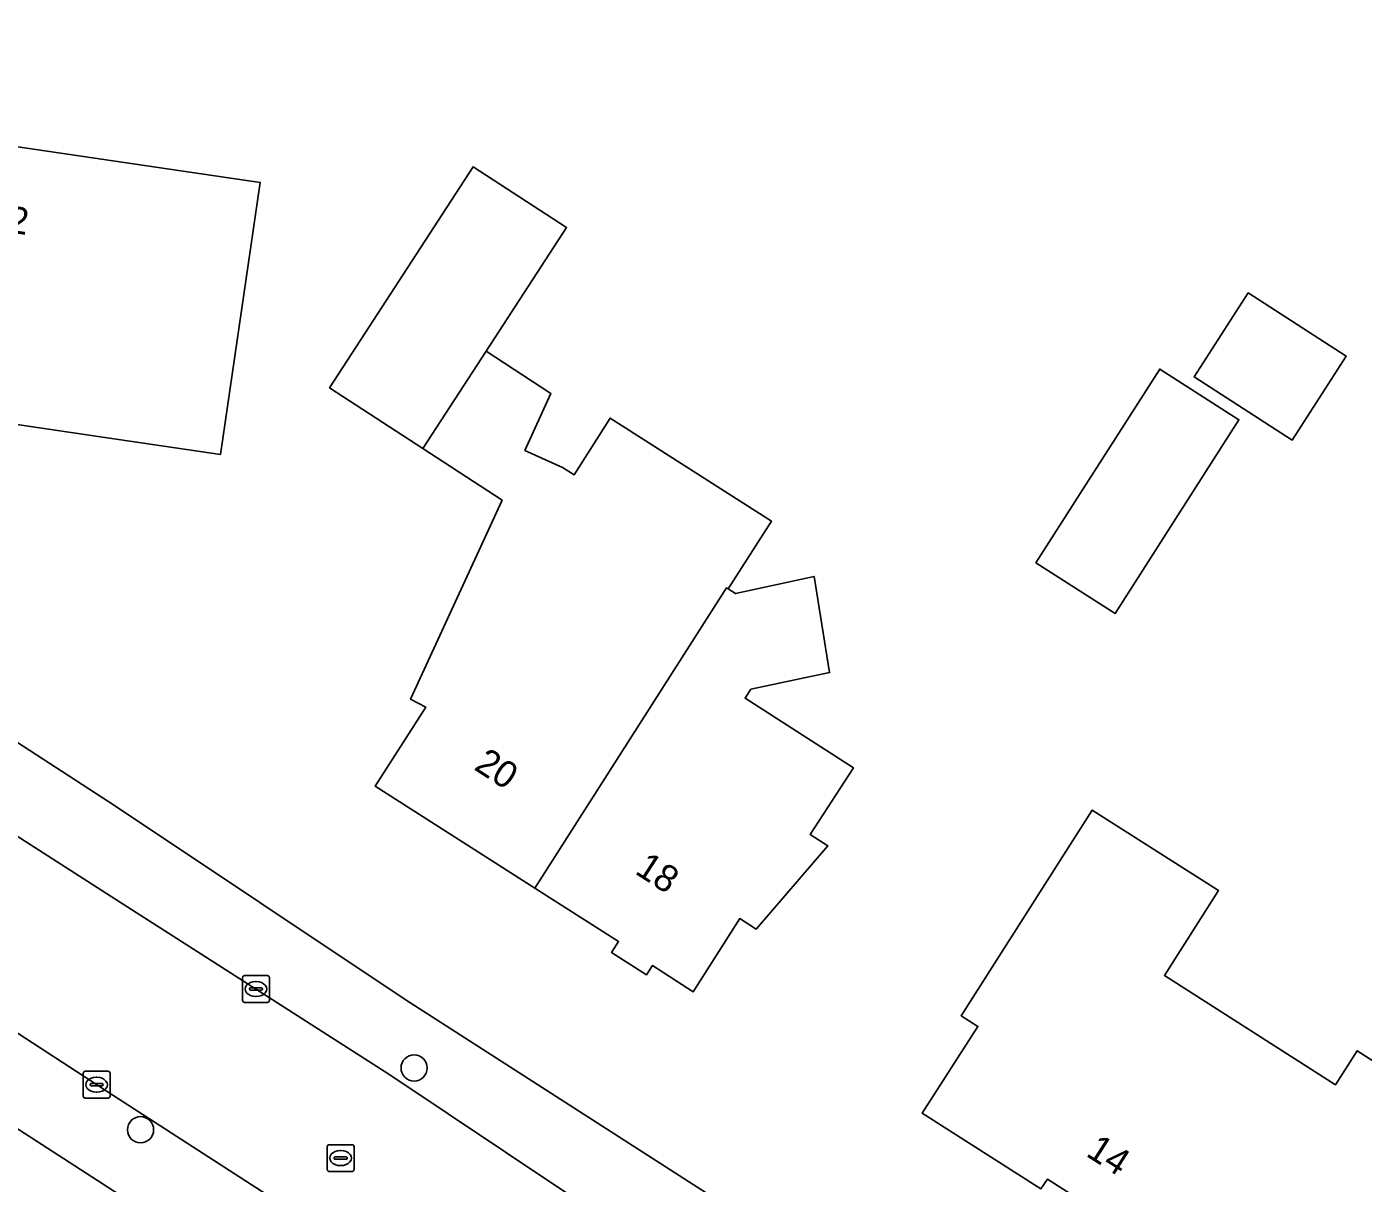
# Model space of a CAD drawing. Extents: x 161139 to 161601, y 381708 to 382245.
# Drawn here: x 161296.54 to 161346.45, y 381974.24 to 382017.42 of the extents above; entities that cross this region are included whole.
import ezdxf

# ---------------------------------------------------------------- set-up
doc = ezdxf.new("R2010")
doc.units = 0
for name, color, linetype in [('IMGEO_Boom', 7, 'Continuous'), ('IMGEO_Erf', 7, 'Continuous'), ('IMGEO_Kolk', 7, 'Continuous'), ('IMGEO_Pand', 7, 'Continuous'), ('IMGEO_Pand_nummerreeks', 7, 'Continuous'), ('IMGEO_Rijbaan_lokaal_open', 7, 'Continuous'), ('IMGEO_Rioolput', 7, 'Continuous'), ('IMGEO_Voetpad_open', 7, 'Continuous')]:
    doc.layers.add(name, color=color, linetype=linetype)

msp = doc.modelspace()

# ---------------------------------------------------------------- linework, layer by layer
at = {"layer": 'IMGEO_Boom'}
for centre in [(161311.007, 381978.547), (161300.792, 381976.24)]:
    msp.add_circle(centre, 0.489, dxfattribs=at)
at = {"layer": 'IMGEO_Erf'}
for points in [[(161301.893, 382073.339), (161290.838, 382055.877), (161287.538, 382048.363), (161285.187, 382041.077), (161283.628, 382034.817), (161278.294, 382002.287), (161281.877, 382000), (161299.823, 381988.353), (161310.674, 381981.109), (161322.611, 381973.432), (161322.712, 381973.551), (161378.924, 381936.994), (161385.641, 381932.206), (161392.817, 381926.552), (161429.313, 381896.994)], [(161370.462, 381928.258), (161276.309, 381989.126), (161276.14, 381989.025), (161267.873, 381937.797), (161267.435, 381933.784), (161267.467, 381929.855), (161267.871, 381925.589), (161268.634, 381921.624), (161269.796, 381917.444), (161271.533, 381912.948), (161272.783, 381910.378), (161277.045, 381903.774)]]:
    msp.add_lwpolyline(points, dxfattribs=at)
for points in [[(161303.775, 382001.453), (161299.54, 382002.074), (161295.582, 382002.654), (161295.956, 382005.206), (161293.903, 382005.507), (161294.186, 382007.443), (161286.609, 382008.553), (161287.441, 382014.225), (161292.389, 382013.5), (161301.029, 382012.233), (161305.264, 382011.612)], [(161322.733, 381996.437), (161323.014, 381996.257), (161325.944, 381996.899), (161326.519, 381993.307), (161323.584, 381992.685), (161323.366, 381992.35), (161327.411, 381989.759), (161325.791, 381987.268), (161326.455, 381986.845), (161323.779, 381983.735), (161323.17, 381984.124), (161321.429, 381981.396), (161319.905, 381982.369), (161319.684, 381982.022), (161318.379, 381982.855), (161318.642, 381983.266), (161315.516, 381985.262), (161309.559, 381989.066), (161311.443, 381992.018), (161310.875, 381992.313), (161314.292, 381999.751), (161311.336, 382001.672), (161307.849, 382003.938), (161313.212, 382012.191), (161316.699, 382009.925), (161313.698, 382005.307), (161316.118, 382003.727), (161315.145, 382001.608), (161316.552, 382000.963), (161316.978, 382000.69), (161318.331, 382002.81), (161324.352, 381998.967)], [(161343.792, 382001.991), (161340.135, 382004.348), (161342.156, 382007.484), (161345.814, 382005.126)], [(161337.186, 381995.52), (161334.228, 381997.409), (161335.883, 382000), (161338.848, 382004.642), (161341.806, 382002.753)], [(161345.229, 381971.099), (161345.094, 381971.185), (161344.863, 381970.822), (161342.904, 381972.07), (161342.662, 381971.691), (161342.021, 381972.099), (161340.338, 381969.467), (161336.1, 381972.176), (161336.689, 381973.098), (161334.659, 381974.396), (161334.413, 381974.038), (161329.982, 381976.855), (161332.06, 381980.096), (161331.431, 381980.495), (161336.33, 381988.176), (161341.044, 381985.169), (161339.024, 381982.002), (161345.419, 381977.923), (161346.226, 381979.188), (161349.184, 381977.301)]]:
    msp.add_lwpolyline(points, close=True, dxfattribs=at)
at = {"layer": 'IMGEO_Kolk'}
for p, q in [((161304.601, 381981.069), (161304.601, 381981.921)), ((161304.676, 381981.995), (161305.528, 381981.995)), ((161305.602, 381981.921), (161305.602, 381981.069)), ((161304.86, 381981.489), (161304.86, 381981.501)), ((161305.298, 381981.452), (161304.9, 381981.452)), ((161304.903, 381981.538), (161305.301, 381981.538)), ((161305.089, 381981.775), (161305.114, 381981.775)), ((161305.344, 381981.501), (161305.344, 381981.489)), ((161305.528, 381980.995), (161304.676, 381980.995)), ((161305.112, 381981.215), (161305.087, 381981.215)), ((161298.726, 381978.422), (161299.578, 381978.422)), ((161298.651, 381977.496), (161298.651, 381978.348)), ((161298.91, 381977.916), (161298.91, 381977.928)), ((161299.348, 381977.879), (161298.95, 381977.879)), ((161298.953, 381977.965), (161299.351, 381977.965)), ((161299.139, 381978.202), (161299.164, 381978.202)), ((161299.394, 381977.928), (161299.394, 381977.916)), ((161299.652, 381978.348), (161299.652, 381977.496)), ((161299.578, 381977.422), (161298.726, 381977.422)), ((161299.162, 381977.642), (161299.137, 381977.642))]:
    msp.add_line(p, q, dxfattribs=at)
for points in [[(161304.601, 381981.069), (161304.601, 381981.921)], [(161304.676, 381981.995), (161305.528, 381981.995)], [(161305.602, 381981.921), (161305.602, 381981.069)], [(161305.528, 381980.995), (161304.676, 381980.995)], [(161298.726, 381978.422), (161299.578, 381978.422)], [(161298.651, 381977.496), (161298.651, 381978.348)], [(161299.652, 381978.348), (161299.652, 381977.496)], [(161299.578, 381977.422), (161298.726, 381977.422)]]:
    msp.add_lwpolyline(points, dxfattribs=at)
for centre, radius, start, end in [((161304.678, 381981.919), 0.0765, 91.552, 178.448), ((161304.678, 381981.919), 0.0765, 91.552, 178.448), ((161305.526, 381981.919), 0.0765, 1.552, 88.448), ((161305.526, 381981.919), 0.0765, 1.552, 88.448), ((161304.9, 381981.498), 0.0403, 85.8775, 175.7526), ((161304.897, 381981.488), 0.0366, 178.938, 274.7102), ((161305.301, 381981.495), 0.043, 264.8664, 352.4533), ((161305.305, 381981.5), 0.0386, 1.7309, 96.639), ((161304.678, 381981.071), 0.0765, 181.552, 268.448), ((161304.678, 381981.071), 0.0765, 181.552, 268.448), ((161305.526, 381981.071), 0.0765, 271.552, 358.448), ((161305.526, 381981.071), 0.0765, 271.552, 358.448), ((161298.728, 381978.346), 0.0765, 91.552, 178.448), ((161298.728, 381978.346), 0.0765, 91.552, 178.448), ((161299.576, 381978.346), 0.0765, 1.552, 88.448), ((161299.576, 381978.346), 0.0765, 1.552, 88.448), ((161298.95, 381977.925), 0.0403, 85.8775, 175.7526), ((161298.947, 381977.915), 0.0366, 178.938, 274.7102), ((161299.351, 381977.922), 0.043, 264.8664, 352.4533), ((161299.355, 381977.927), 0.0386, 1.7309, 96.639), ((161298.728, 381977.498), 0.0765, 181.552, 268.448), ((161298.728, 381977.498), 0.0765, 181.552, 268.448), ((161299.576, 381977.498), 0.0765, 271.552, 358.448), ((161299.576, 381977.498), 0.0765, 271.552, 358.448)]:
    msp.add_arc(centre, radius, start, end, dxfattribs=at)
for centre, major_axis, ratio, start_param, end_param in [((161305.088, 381981.495), (-0.387, 0.002), 0.722429, 4.712389, 7.853982), ((161305.113, 381981.495), (-0.39, 0.002), 0.717154, 1.570796, 4.712389), ((161299.138, 381977.922), (-0.387, 0.002), 0.722429, 4.712389, 7.853982), ((161299.163, 381977.922), (-0.39, 0.002), 0.717154, 1.570796, 4.712389)]:
    msp.add_ellipse(centre, major_axis=major_axis, ratio=ratio, start_param=start_param, end_param=end_param, dxfattribs=at)
at = {"layer": 'IMGEO_Pand'}
for points in [[(161292.389, 382013.5), (161287.441, 382014.225), (161286.609, 382008.553), (161294.186, 382007.443), (161293.903, 382005.507), (161295.956, 382005.206), (161295.582, 382002.654), (161299.54, 382002.074), (161303.775, 382001.453), (161305.264, 382011.612), (161301.029, 382012.233)], [(161316.699, 382009.925), (161313.212, 382012.191), (161307.849, 382003.938), (161311.336, 382001.672), (161313.698, 382005.307)], [(161342.156, 382007.484), (161340.135, 382004.348), (161343.792, 382001.991), (161345.814, 382005.126)], [(161322.589, 381996.335), (161322.677, 381996.473), (161322.733, 381996.437), (161324.352, 381998.967), (161318.331, 382002.81), (161316.978, 382000.69), (161316.552, 382000.963), (161315.145, 382001.608), (161316.118, 382003.727), (161313.698, 382005.307), (161311.336, 382001.672), (161314.292, 381999.751), (161310.875, 381992.313), (161311.443, 381992.018), (161309.559, 381989.066), (161315.516, 381985.262)], [(161341.806, 382002.753), (161338.848, 382004.642), (161335.883, 382000), (161334.228, 381997.409), (161337.186, 381995.52)], [(161327.411, 381989.759), (161323.366, 381992.35), (161323.584, 381992.685), (161326.519, 381993.307), (161325.944, 381996.899), (161323.014, 381996.257), (161322.733, 381996.437), (161322.677, 381996.473), (161322.589, 381996.335), (161315.516, 381985.262), (161318.642, 381983.266), (161318.379, 381982.855), (161319.684, 381982.022), (161319.905, 381982.369), (161321.429, 381981.396), (161323.17, 381984.124), (161323.779, 381983.735), (161326.455, 381986.845), (161325.791, 381987.268)], [(161349.184, 381977.301), (161346.226, 381979.188), (161345.419, 381977.923), (161339.024, 381982.002), (161341.044, 381985.169), (161336.33, 381988.176), (161331.431, 381980.495), (161332.06, 381980.096), (161329.982, 381976.855), (161334.413, 381974.038), (161334.659, 381974.396), (161336.689, 381973.098), (161336.1, 381972.176), (161340.338, 381969.467), (161342.021, 381972.099), (161342.662, 381971.691), (161342.904, 381972.07), (161344.863, 381970.822), (161345.094, 381971.185), (161345.229, 381971.099)]]:
    msp.add_lwpolyline(points, close=True, dxfattribs=at)
at = {"layer": 'IMGEO_Rijbaan_lokaal_open'}
for points in [[(161354.44, 381949.434), (161345.5, 381955.194), (161345.132, 381955.433), (161341.968, 381957.49), (161334.965, 381962.043), (161325.373, 381968.263), (161318.237, 381972.89), (161316.637, 381973.927), (161310.106, 381978.294), (161303.837, 381982.304), (161300.012, 381984.75), (161296.327, 381987.12), (161278.737, 381998.431)], [(161278.323, 381991.478), (161299.753, 381977.533), (161307.482, 381972.536), (161311.114, 381970.18), (161315.062, 381967.62), (161315.173, 381967.548), (161318.89, 381965.138), (161327.462, 381959.489), (161330.866, 381957.332), (161337.714, 381952.958), (161346.638, 381947.161), (161350.625, 381944.584), (161357.825, 381939.931), (161366.222, 381934.52), (161372.037, 381930.857), (161375.083, 381928.811)]]:
    msp.add_lwpolyline(points, dxfattribs=at)
at = {"layer": 'IMGEO_Rioolput'}
for p, q in [((161307.763, 381974.755), (161307.763, 381975.607)), ((161307.838, 381975.681), (161308.69, 381975.681)), ((161308.251, 381975.461), (161308.276, 381975.461)), ((161308.764, 381975.607), (161308.764, 381974.755)), ((161308.022, 381975.175), (161308.022, 381975.187)), ((161308.46, 381975.138), (161308.062, 381975.138)), ((161308.065, 381975.224), (161308.463, 381975.224)), ((161308.274, 381974.901), (161308.249, 381974.901)), ((161308.506, 381975.187), (161308.506, 381975.175)), ((161308.69, 381974.681), (161307.838, 381974.681))]:
    msp.add_line(p, q, dxfattribs=at)
for points in [[(161307.763, 381974.755), (161307.763, 381975.607)], [(161307.838, 381975.681), (161308.69, 381975.681)], [(161308.764, 381975.607), (161308.764, 381974.755)], [(161308.69, 381974.681), (161307.838, 381974.681)]]:
    msp.add_lwpolyline(points, dxfattribs=at)
for centre, radius, start, end in [((161307.84, 381975.605), 0.0765, 91.552, 178.448), ((161307.84, 381975.605), 0.0765, 91.552, 178.448), ((161308.688, 381975.605), 0.0765, 1.552, 88.448), ((161308.688, 381975.605), 0.0765, 1.552, 88.448), ((161308.062, 381975.184), 0.0403, 85.8775, 175.7526), ((161308.059, 381975.174), 0.0366, 178.938, 274.7102), ((161308.463, 381975.181), 0.043, 264.8664, 352.4533), ((161308.467, 381975.186), 0.0386, 1.7309, 96.639), ((161307.84, 381974.757), 0.0765, 181.552, 268.448), ((161307.84, 381974.757), 0.0765, 181.552, 268.448), ((161308.688, 381974.757), 0.0765, 271.552, 358.448), ((161308.688, 381974.757), 0.0765, 271.552, 358.448)]:
    msp.add_arc(centre, radius, start, end, dxfattribs=at)
for centre, major_axis, ratio, start_param, end_param in [((161308.25, 381975.181), (-0.387, 0.002), 0.722429, 4.712389, 7.853982), ((161308.275, 381975.181), (-0.39, 0.002), 0.717154, 1.570796, 4.712389)]:
    msp.add_ellipse(centre, major_axis=major_axis, ratio=ratio, start_param=start_param, end_param=end_param, dxfattribs=at)
at = {"layer": 'IMGEO_Voetpad_open'}
for points in [[(161392.817, 381926.552), (161385.641, 381932.206), (161378.924, 381936.994), (161322.712, 381973.551), (161322.611, 381973.432), (161310.674, 381981.109), (161299.823, 381988.353), (161281.877, 382000)], [(161327.462, 381959.489), (161318.89, 381965.138), (161315.173, 381967.548), (161315.062, 381967.62), (161311.114, 381970.18), (161307.482, 381972.536), (161299.753, 381977.533), (161278.323, 381991.478), (161276.309, 381989.126), (161370.462, 381928.258), (161376.195, 381924.445)], [(161296.327, 381987.12), (161300.012, 381984.75), (161303.837, 381982.304), (161310.106, 381978.294), (161316.637, 381973.927), (161318.237, 381972.89), (161325.373, 381968.263), (161334.965, 381962.043), (161341.968, 381957.49), (161345.132, 381955.433), (161345.5, 381955.194), (161354.44, 381949.434), (161361.946, 381944.451), (161364.318, 381942.933), (161367.432, 381940.939), (161370.251, 381939.135), (161376.383, 381935.18), (161381.315, 381931.756), (161381.728, 381931.469), (161384.971, 381929.006)]]:
    msp.add_lwpolyline(points, dxfattribs=at)

# ---------------------------------------------------------------- texts
at = {"layer": 'IMGEO_Pand_nummerreeks'}
for s, rotation, p in [('22', 351.6657, (161295.065, 382009.861)), ('20', 327.1294, (161313.203, 381989.712)), ('18', 327.1294, (161319.214, 381985.827)), ('14', 327.4044, (161336.056, 381975.284))]:
    msp.add_text(s, height=1, rotation=rotation, dxfattribs=at).set_placement(p)

doc.saveas('drawing.dxf')
